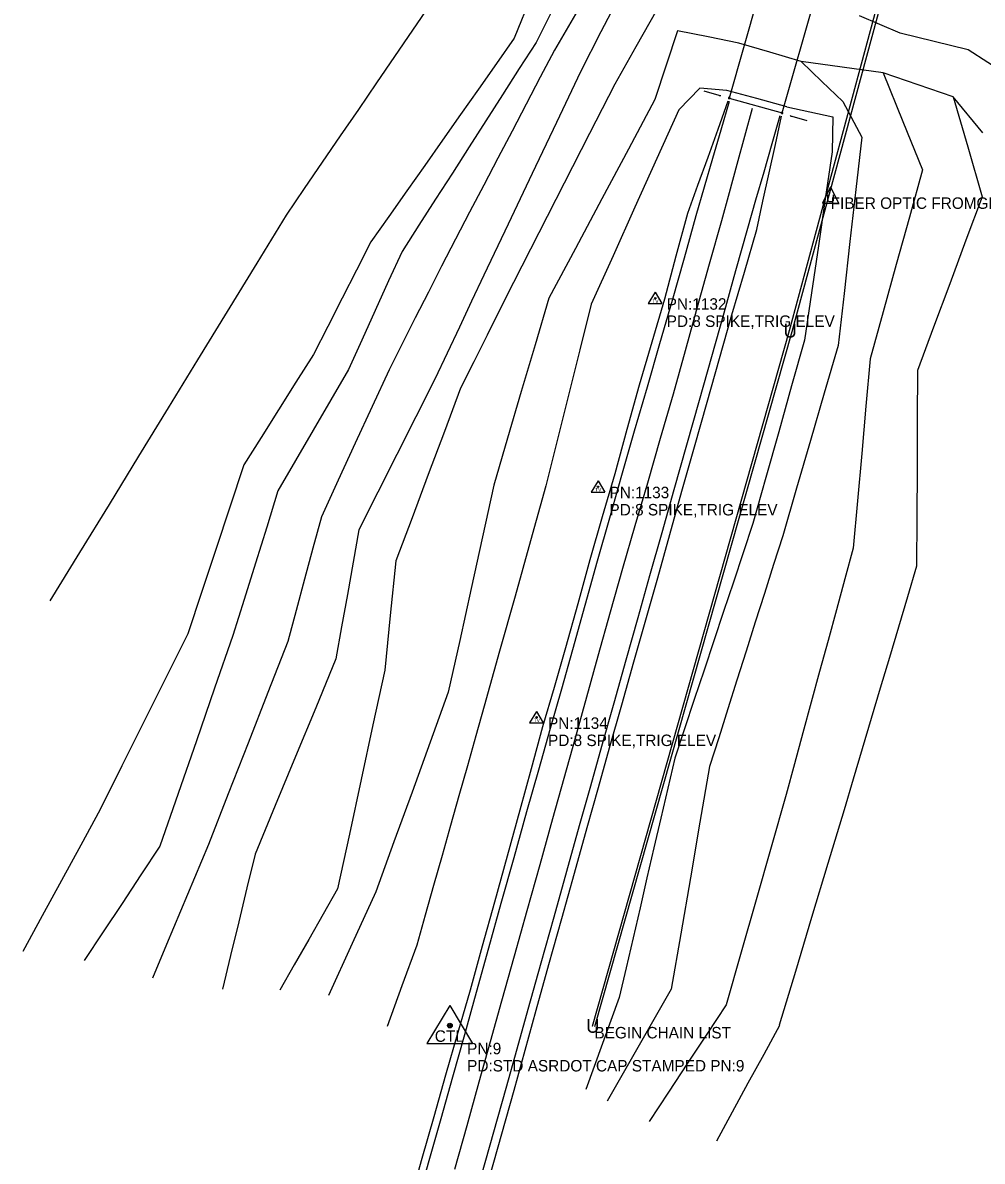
# Model space of a CAD drawing. Extents: x 1445297 to 1476720, y 2042269 to 2057889.
# Drawn here: x 1445766.9 to 1446184.7, y 2055038.2 to 2055534.2 of the extents above; entities that cross this region are included whole.
import ezdxf

# ---------------------------------------------------------------- set-up
doc = ezdxf.new("R2010")
doc.units = 0
for name, color, linetype in [('S_BRIDGE', 7, 'Continuous'), ('S_DITCHLINE', 7, 'Continuous'), ('S_EDGE_PAVEMENT', 7, 'Continuous'), ('S_FIBER_OPTIC_CABLE', 7, 'Continuous'), ('S_PAVEMENT_CROWN', 7, 'Continuous'), ('S_PRIMARY_CTL', 7, 'Continuous'), ('S_PRIMARY_CTL_ANNOT', 7, 'Continuous'), ('S_SECONDARY_CTL', 7, 'Continuous'), ('S_SECONDARY_CTL_ANNOT', 7, 'Continuous'), ('S_SHOULDER', 7, 'Continuous'), ('S_STR_PT_SYM', 7, 'Continuous'), ('S_STREAM', 7, 'Continuous'), ('S_TREE', 7, 'Continuous'), ('S_UNDERGROUND_CABLE', 7, 'Continuous'), ('S_UNDERGROUND_CABLE_ANNOT', 7, 'Continuous'), ('S_UTILITY_POLE', 7, 'Continuous'), ('S_UTILITY_POLE_ANNOT', 7, 'Continuous'), ('S_UTL_PT_SYM', 7, 'Continuous'), ('S_WALL', 7, 'Continuous')]:
    doc.layers.add(name, color=color, linetype=linetype)

msp = doc.modelspace()

# ---------------------------------------------------------------- linework, layer by layer
at = {"layer": 'S_BRIDGE'}
for p, q in [((1446101.76, 2055597.5), (1446074.53, 2055501.41)), ((1446097.53, 2055494.89), (1446124.93, 2055591.15)), ((1446074.53, 2055501.41), (1446097.53, 2055494.89))]:
    msp.add_line(p, q, dxfattribs=at)
at = {"layer": 'S_DITCHLINE'}
for points in [[(1445988.57, 2055546.55), (1445980.92, 2055527.54), (1445973.11, 2055516.44), (1445965.31, 2055505.33), (1445957.5, 2055494.23), (1445949.7, 2055483.12), (1445941.9, 2055472.01), (1445934.09, 2055460.91), (1445926.29, 2055449.8), (1445918.48, 2055438.7), (1445912.22, 2055426.43), (1445905.96, 2055414.17), (1445899.69, 2055401.91), (1445893.43, 2055389.65), (1445885.85, 2055377.62), (1445878.27, 2055365.6), (1445870.68, 2055353.57), (1445863.1, 2055341.54), (1445857, 2055323.16), (1445850.91, 2055304.77), (1445844.81, 2055286.38), (1445838.72, 2055268), (1445829.17, 2055248.84), (1445819.63, 2055229.69), (1445810.08, 2055210.54), (1445800.54, 2055191.39), (1445792.12, 2055175.95), (1445783.71, 2055160.5), (1445775.29, 2055145.06), (1445766.88, 2055129.62)], [(1446027.55, 2055547.55), (1446018.67, 2055530.18), (1446009.78, 2055512.82), (1445999.25, 2055490.68), (1445988.72, 2055468.55), (1445978.18, 2055446.41), (1445967.65, 2055424.28), (1445962.32, 2055412.94), (1445957, 2055401.61), (1445951.67, 2055390.28), (1445946.34, 2055378.95), (1445938.05, 2055362.52), (1445929.76, 2055346.09), (1445921.47, 2055329.66), (1445913.19, 2055313.23), (1445910.7, 2055299.18), (1445908.22, 2055285.14), (1445905.74, 2055271.1), (1445903.25, 2055257.05), (1445894.45, 2055235.78), (1445885.65, 2055214.52), (1445876.84, 2055193.25), (1445868.04, 2055171.98), (1445864.49, 2055157.27), (1445860.94, 2055142.56), (1445857.39, 2055127.85), (1445853.84, 2055113.14)], [(1445999.14, 2055543.07), (1445990.41, 2055525.62), (1445983.11, 2055514.25), (1445975.82, 2055502.87), (1445968.53, 2055491.49), (1445961.24, 2055480.12), (1445953.94, 2055468.74), (1445946.65, 2055457.36), (1445939.36, 2055445.99), (1445932.06, 2055434.61), (1445926.21, 2055421.73), (1445920.36, 2055408.85), (1445914.51, 2055395.98), (1445908.66, 2055383.1), (1445900.99, 2055369.88), (1445893.33, 2055356.66), (1445885.66, 2055343.45), (1445878, 2055330.23), (1445873.1, 2055314.48), (1445868.2, 2055298.72), (1445863.31, 2055282.97), (1445858.41, 2055267.21), (1445850.43, 2055244.26), (1445842.46, 2055221.31), (1445834.48, 2055198.35), (1445826.5, 2055175.4), (1445818.3, 2055162.96), (1445810.09, 2055150.52), (1445801.88, 2055138.09), (1445793.67, 2055125.65)], [(1446008.57, 2055539.67), (1445998.37, 2055522.29), (1445992.22, 2055510.53), (1445986.07, 2055498.77), (1445979.92, 2055487.01), (1445973.77, 2055475.25), (1445967.63, 2055463.48), (1445961.48, 2055451.72), (1445955.33, 2055439.96), (1445949.18, 2055428.2), (1445943.5, 2055416.9), (1445937.81, 2055405.6), (1445932.13, 2055394.31), (1445926.44, 2055383.01), (1445919.06, 2055366.99), (1445911.67, 2055350.98), (1445904.29, 2055334.96), (1445896.9, 2055318.94), (1445893.24, 2055305.35), (1445889.58, 2055291.76), (1445885.92, 2055278.17), (1445882.26, 2055264.57), (1445873.63, 2055242.48), (1445864.99, 2055220.38), (1445856.36, 2055198.29), (1445847.72, 2055176.19), (1445841.63, 2055161.65), (1445835.55, 2055147.11), (1445829.46, 2055132.56), (1445823.38, 2055118.02)], [(1446043.06, 2055539.85), (1446033.86, 2055523.68), (1446024.67, 2055507.52), (1446013.65, 2055485.92), (1446002.62, 2055464.32), (1445991.6, 2055442.71), (1445980.57, 2055421.11), (1445974.81, 2055409.58), (1445969.05, 2055398.04), (1445963.29, 2055386.51), (1445957.53, 2055374.97), (1445950.48, 2055356.16), (1445943.44, 2055337.35), (1445936.39, 2055318.54), (1445929.35, 2055299.73), (1445926.93, 2055275.96), (1445924.51, 2055252.18), (1445919.38, 2055228.36), (1445914.25, 2055204.54), (1445909.12, 2055180.73), (1445903.99, 2055156.91), (1445897.7, 2055145.86), (1445891.42, 2055134.82), (1445885.13, 2055123.77), (1445878.85, 2055112.73)], [(1446299.1, 2055378.25), (1446294.17, 2055392.37), (1446289.24, 2055406.49), (1446284.31, 2055420.62), (1446279.38, 2055434.74), (1446269.61, 2055451.33), (1446259.85, 2055467.93), (1446248.1, 2055476.05), (1446236.35, 2055484.18), (1446224.6, 2055492.31), (1446212.84, 2055500.44), (1446195.69, 2055511.4), (1446178.54, 2055522.35), (1446163.75, 2055526.02), (1446148.96, 2055529.68), (1446131.24, 2055537.2)], [(1446184.97, 2055486.27), (1446172.06, 2055501.87), (1446156.84, 2055507.13), (1446141.62, 2055512.4), (1446123.7, 2055514.86), (1446105.78, 2055517.32), (1446092.22, 2055521.34), (1446078.67, 2055525.35), (1446065.36, 2055528.04), (1446052.05, 2055530.73), (1446047.12, 2055515.74), (1446042.18, 2055500.74), (1446030.62, 2055479.1), (1446019.06, 2055457.47), (1446007.5, 2055435.83), (1445995.94, 2055414.2), (1445989.95, 2055393.85), (1445983.96, 2055373.51), (1445977.98, 2055353.16), (1445971.99, 2055332.82), (1445967.04, 2055310.24), (1445962.09, 2055287.67), (1445957.14, 2055265.1), (1445952.19, 2055242.52), (1445944.3, 2055220.78), (1445936.41, 2055199.04), (1445928.52, 2055177.3), (1445920.63, 2055155.56), (1445910.33, 2055133), (1445900.04, 2055110.44)], [(1446105.78, 2055517.32), (1446114.85, 2055508.59), (1446123.92, 2055499.85), (1446132.27, 2055484.3), (1446129.68, 2055461.62), (1446127.1, 2055438.95), (1446124.51, 2055416.27), (1446121.93, 2055393.59), (1446115.9, 2055372.87), (1446109.88, 2055352.15), (1446103.86, 2055331.44), (1446097.83, 2055310.72), (1446093.85, 2055298.14), (1446089.86, 2055285.57), (1446085.87, 2055272.99), (1446081.88, 2055260.42), (1446077.9, 2055247.85), (1446073.91, 2055235.27), (1446069.92, 2055222.7), (1446065.93, 2055210.12), (1446061.77, 2055185.87), (1446057.6, 2055161.61), (1446053.43, 2055137.35), (1446049.27, 2055113.1), (1446042.28, 2055100.91), (1446035.29, 2055088.73), (1446028.3, 2055076.54), (1446021.32, 2055064.36)], [(1446141.62, 2055512.4), (1446150.13, 2055491.25), (1446158.65, 2055470.11), (1446152.95, 2055449.52), (1446147.25, 2055428.92), (1446141.56, 2055408.33), (1446135.86, 2055387.74), (1446134.03, 2055367.13), (1446132.19, 2055346.52), (1446130.36, 2055325.91), (1446128.53, 2055305.29), (1446124.87, 2055291.88), (1446121.21, 2055278.47), (1446117.55, 2055265.05), (1446113.89, 2055251.64), (1446110.23, 2055238.23), (1446106.57, 2055224.81), (1446102.91, 2055211.4), (1446099.25, 2055197.98), (1446092.73, 2055175.07), (1446086.21, 2055152.15), (1446079.69, 2055129.23), (1446073.17, 2055106.32), (1446064.78, 2055093.62), (1446056.4, 2055080.93), (1446048.01, 2055068.24), (1446039.62, 2055055.54)], [(1446172.06, 2055501.87), (1446178.36, 2055480.12), (1446184.67, 2055458.37), (1446177.62, 2055439.44), (1446170.58, 2055420.51), (1446163.54, 2055401.58), (1446156.49, 2055382.65), (1446156.39, 2055361.34), (1446156.29, 2055340.03), (1446156.18, 2055318.71), (1446156.08, 2055297.4), (1446152.13, 2055284.14), (1446148.19, 2055270.88), (1446144.24, 2055257.63), (1446140.3, 2055244.37), (1446136.35, 2055231.11), (1446132.4, 2055217.85), (1446128.46, 2055204.59), (1446124.51, 2055191.34), (1446117.46, 2055167.87), (1446110.41, 2055144.4), (1446103.35, 2055120.93), (1446096.3, 2055097.47), (1446096.42, 2055097.31), (1446089.55, 2055084.73), (1446082.67, 2055072.16), (1446075.8, 2055059.58), (1446068.92, 2055047.01)]]:
    msp.add_lwpolyline(points, dxfattribs=at)
at = {"layer": 'S_EDGE_PAVEMENT'}
for points in [[(1445938.52, 2055019.41), (1445943.91, 2055038.59), (1445949.02, 2055056.8), (1445954.14, 2055075), (1445959.31, 2055093.43), (1445964.48, 2055111.86), (1445969.86, 2055131.22), (1445975.25, 2055150.57), (1445980.84, 2055170.55), (1445986.44, 2055190.52), (1445991.57, 2055208.73), (1445996.69, 2055226.94), (1446001.56, 2055244.03), (1446006.42, 2055261.13), (1446011.8, 2055280.47), (1446017.18, 2055299.81), (1446022.46, 2055318.48), (1446027.74, 2055337.15), (1446033.32, 2055356.41), (1446038.9, 2055375.66), (1446044.33, 2055394.51), (1446049.75, 2055413.35), (1446054.97, 2055431.76), (1446060.19, 2055450.18), (1446063.78, 2055462.66), (1446067.38, 2055475.14), (1446070.97, 2055487.62), (1446074.57, 2055500.1)], [(1445966.63, 2055031.96), (1445972, 2055050.98), (1445977.38, 2055070), (1445982.18, 2055087.21), (1445986.99, 2055104.42), (1445992.66, 2055124.59), (1445998.34, 2055144.75), (1446003.86, 2055164.59), (1446009.38, 2055184.42), (1446014.22, 2055201.76), (1446019.06, 2055219.09), (1446024.38, 2055237.9), (1446029.69, 2055256.71), (1446034.84, 2055275.06), (1446040, 2055293.4), (1446045.26, 2055312.15), (1446050.52, 2055330.9), (1446056.07, 2055350.31), (1446061.63, 2055369.72), (1446066.95, 2055388.81), (1446072.28, 2055407.89), (1446077.46, 2055426.31), (1446082.64, 2055444.73), (1446086.15, 2055457), (1446089.66, 2055469.27), (1446093.17, 2055481.53), (1446096.68, 2055493.8)]]:
    msp.add_lwpolyline(points, dxfattribs=at)
at = {"layer": 'S_FIBER_OPTIC_CABLE'}
for p, q in [((1446184.54, 2055711.05), (1446100.6, 2055399.96)), ((1446100.6, 2055399.96), (1446014.81, 2055096.89))]:
    msp.add_line(p, q, dxfattribs=at)
at = {"layer": 'S_PAVEMENT_CROWN'}
msp.add_lwpolyline([(1445955.04, 2055034.8), (1445960.36, 2055053.8), (1445965.68, 2055072.8), (1445970.62, 2055090.43), (1445975.55, 2055108.06), (1445981.04, 2055127.75), (1445986.52, 2055147.44), (1445992.13, 2055167.46), (1445997.74, 2055187.48), (1446002.62, 2055205.06), (1446007.5, 2055222.64), (1446012.49, 2055240.54), (1446017.48, 2055258.43), (1446022.82, 2055277.53), (1446028.17, 2055296.63), (1446033.61, 2055315.21), (1446039.06, 2055333.8), (1446044.63, 2055353.17), (1446050.21, 2055372.54), (1446055.42, 2055391.46), (1446060.63, 2055410.38), (1446065.94, 2055429.2), (1446071.24, 2055448.02), (1446074.59, 2055460.28), (1446077.95, 2055472.53), (1446081.3, 2055484.79), (1446084.66, 2055497.04)], dxfattribs=at)
at = {"layer": 'S_PRIMARY_CTL'}
for p, q in [((1445952.88, 2055106.01), (1445942.84, 2055089.5)), ((1445952.88, 2055106.01), (1445962.7, 2055089.5)), ((1445942.84, 2055089.5), (1445962.7, 2055089.5))]:
    msp.add_line(p, q, dxfattribs=at)
for radius in [1.04, 0.609, 0.344]:
    msp.add_circle((1445952.88, 2055097.31), radius, dxfattribs=at)
at = {"layer": 'S_SECONDARY_CTL'}
for p, q in [((1446042.29, 2055416.8), (1446039.28, 2055411.84)), ((1446042.29, 2055416.8), (1446045.24, 2055411.84)), ((1446039.28, 2055411.84), (1446045.24, 2055411.84)), ((1446017.37, 2055334.67), (1446014.36, 2055329.72)), ((1446017.37, 2055334.67), (1446020.32, 2055329.72)), ((1446014.36, 2055329.72), (1446020.32, 2055329.72)), ((1445990.61, 2055234.19), (1445987.6, 2055229.24)), ((1445990.61, 2055234.19), (1445993.56, 2055229.24)), ((1445987.6, 2055229.24), (1445993.56, 2055229.24))]:
    msp.add_line(p, q, dxfattribs=at)
for centre, radius in [((1446042.29, 2055414.19), 0.311), ((1446042.29, 2055414.19), 0.183), ((1446042.29, 2055414.19), 0.103), ((1446017.37, 2055332.06), 0.311), ((1446017.37, 2055332.06), 0.183), ((1446017.37, 2055332.06), 0.103), ((1445990.61, 2055231.58), 0.311), ((1445990.61, 2055231.58), 0.183), ((1445990.61, 2055231.58), 0.103)]:
    msp.add_circle(centre, radius, dxfattribs=at)
at = {"layer": 'S_SHOULDER'}
for points in [[(1445935.44, 2055020.19), (1445940.83, 2055039.53), (1445945.97, 2055057.7), (1445951.1, 2055075.86), (1445956.46, 2055094.41), (1445961.81, 2055112.95), (1445967.1, 2055132.08), (1445972.39, 2055151.21), (1445977.9, 2055171.22), (1445983.41, 2055191.23), (1445988.41, 2055209.38), (1445993.41, 2055227.54), (1445998.4, 2055244.79), (1446003.4, 2055262.04), (1446008.68, 2055281.23), (1446013.96, 2055300.43), (1446019.38, 2055319.14), (1446024.8, 2055337.86), (1446030.12, 2055357.13), (1446035.44, 2055376.41), (1446040.93, 2055395.19), (1446046.42, 2055413.98), (1446051.43, 2055432.59), (1446056.44, 2055451.2), (1446060.86, 2055463.43), (1446065.28, 2055475.66), (1446069.7, 2055487.89), (1446074.12, 2055500.12)], [(1445970.08, 2055031.1), (1445975.49, 2055050.1), (1445980.9, 2055069.1), (1445985.66, 2055086.55), (1445990.43, 2055104), (1445996, 2055123.95), (1446001.58, 2055143.91), (1446007.11, 2055163.77), (1446012.64, 2055183.63), (1446017.52, 2055201), (1446022.4, 2055218.36), (1446027.72, 2055237.04), (1446033.04, 2055255.71), (1446038.24, 2055274.07), (1446043.43, 2055292.43), (1446048.62, 2055311.29), (1446053.82, 2055330.14), (1446059.39, 2055349.51), (1446064.96, 2055368.88), (1446070.33, 2055387.89), (1446075.7, 2055406.9), (1446081.1, 2055425.49), (1446086.51, 2055444.08), (1446089.21, 2055456.43), (1446091.91, 2055468.79), (1446094.61, 2055481.15), (1446097.31, 2055493.5)]]:
    msp.add_lwpolyline(points, dxfattribs=at)
at = {"layer": 'S_STR_PT_SYM'}
for points in [[(1446074.53, 2055501.41), (1446074.53, 2055501.91), (1446074.53, 2055501.41), (1446074.03, 2055501.41), (1446074.53, 2055501.41), (1446074.53, 2055500.91), (1446074.53, 2055501.41), (1446075.03, 2055501.41)], [(1446097.53, 2055494.89), (1446097.53, 2055495.39), (1446097.53, 2055494.89), (1446097.03, 2055494.89), (1446097.53, 2055494.89), (1446097.53, 2055494.39), (1446097.53, 2055494.89), (1446098.03, 2055494.89)]]:
    msp.add_lwpolyline(points, dxfattribs=at)
at = {"layer": 'S_STREAM'}
for points in [[(1446099.67, 2055497.56), (1446086.54, 2055501.16), (1446073.41, 2055504.76), (1446061.66, 2055505.66), (1446052.52, 2055496.25), (1446042.98, 2055475.07), (1446033.45, 2055453.9), (1446023.92, 2055432.73), (1446014.39, 2055411.56), (1446009.46, 2055391.78), (1446004.52, 2055372), (1445999.59, 2055352.21), (1445994.65, 2055332.43), (1445987.95, 2055308.45), (1445981.24, 2055284.46), (1445974.53, 2055260.48), (1445967.82, 2055236.49), (1445964.15, 2055223.47), (1445960.48, 2055210.45), (1445956.81, 2055197.43), (1445953.14, 2055184.41), (1445949.47, 2055171.39), (1445945.8, 2055158.37), (1445942.13, 2055145.34), (1445938.46, 2055132.32), (1445932.01, 2055114.63), (1445925.56, 2055096.94)], [(1446099.67, 2055497.56), (1446119.58, 2055493.17), (1446119.31, 2055477.97), (1446116.31, 2055457.48), (1446113.32, 2055436.98), (1446110.32, 2055416.48), (1446107.32, 2055395.99), (1446101.7, 2055376.02), (1446096.08, 2055356.04), (1446090.46, 2055336.07), (1446084.84, 2055316.1), (1446080.58, 2055303.31), (1446076.32, 2055290.53), (1446072.06, 2055277.74), (1446067.81, 2055264.95), (1446063.55, 2055252.17), (1446059.29, 2055239.38), (1446055.03, 2055226.59), (1446050.77, 2055213.81), (1446047.75, 2055200.77), (1446044.73, 2055187.73), (1446041.71, 2055174.69), (1446038.68, 2055161.65), (1446035.66, 2055148.61), (1446032.64, 2055135.57), (1446029.61, 2055122.53), (1446026.59, 2055109.49), (1446019.31, 2055089.5), (1446012.03, 2055069.52)]]:
    msp.add_lwpolyline(points, dxfattribs=at)
at = {"layer": 'S_TREE'}
msp.add_lwpolyline([(1445944.45, 2055542.5), (1445936.59, 2055530.99), (1445928.73, 2055519.49), (1445920.88, 2055507.98), (1445913.02, 2055496.47), (1445905.16, 2055484.97), (1445897.3, 2055473.46), (1445889.44, 2055461.96), (1445881.58, 2055450.45), (1445868.73, 2055429.44), (1445855.87, 2055408.42), (1445843.01, 2055387.41), (1445830.15, 2055366.39), (1445817.29, 2055345.38), (1445804.43, 2055324.37), (1445791.57, 2055303.35), (1445778.72, 2055282.34)], dxfattribs=at)
at = {"layer": 'S_UNDERGROUND_CABLE'}
for p, q in [((1446186.26, 2055711.49), (1446101.82, 2055399.59)), ((1446101.82, 2055399.59), (1446015.83, 2055096.71))]:
    msp.add_line(p, q, dxfattribs=at)
at = {"layer": 'S_UTILITY_POLE'}
for p, q in [((1446118.68, 2055462.67), (1446115.16, 2055455.57)), ((1446118.68, 2055462.67), (1446122.17, 2055455.57)), ((1446115.16, 2055455.57), (1446122.17, 2055455.57)), ((1446117.48, 2055456.81), (1446117.48, 2055459.26)), ((1446118.1, 2055456.16), (1446117.48, 2055456.81)), ((1446119.3, 2055456.16), (1446118.1, 2055456.16)), ((1446119.85, 2055456.81), (1446119.3, 2055456.16)), ((1446119.85, 2055459.26), (1446119.85, 2055456.81))]:
    msp.add_line(p, q, dxfattribs=at)
at = {"layer": 'S_UTL_PT_SYM'}
for points in [[(1446100.6, 2055399.96), (1446100.6, 2055400.01), (1446100.6, 2055399.96), (1446100.55, 2055399.96), (1446100.6, 2055399.96), (1446100.6, 2055399.91), (1446100.6, 2055399.96), (1446100.66, 2055399.96)], [(1446014.81, 2055096.89), (1446014.81, 2055096.94), (1446014.81, 2055096.89), (1446014.76, 2055096.89), (1446014.81, 2055096.89), (1446014.81, 2055096.84), (1446014.81, 2055096.89), (1446014.86, 2055096.89)]]:
    msp.add_lwpolyline(points, dxfattribs=at)
at = {"layer": 'S_WALL'}
for points in [[(1446070.83, 2055502.3), (1446070.31, 2055502.41), (1446070.11, 2055502.46), (1446063.58, 2055504.34)], [(1446101.09, 2055493.73), (1446101.39, 2055493.56), (1446101.71, 2055493.49), (1446108.38, 2055491.65)]]:
    msp.add_lwpolyline(points, dxfattribs=at)

# ---------------------------------------------------------------- texts
at = {"layer": 'S_PRIMARY_CTL'}
msp.add_text('CTL', height=5, dxfattribs=at).set_placement((1445946.29, 2055090.23))
at = {"layer": 'S_PRIMARY_CTL_ANNOT'}
for s, p in [('PN:9', (1445960.38, 2055084.81)), ('PD:STD ASRDOT CAP STAMPED PN:9', (1445960.38, 2055077.31))]:
    msp.add_text(s, height=5, dxfattribs=at).set_placement(p)
at = {"layer": 'S_SECONDARY_CTL'}
for p in [(1446041.09, 2055412.18), (1446016.17, 2055330.05), (1445989.41, 2055229.57)]:
    msp.add_text('TV', height=1.5, dxfattribs=at).set_placement(p)
at = {"layer": 'S_SECONDARY_CTL_ANNOT'}
for s, p in [('PN:1132', (1446047.29, 2055409.19)), ('PD:8 SPIKE,TRIG ELEV', (1446047.29, 2055401.69)), ('PN:1133', (1446022.37, 2055327.06)), ('PD:8 SPIKE,TRIG ELEV', (1446022.37, 2055319.56)), ('PN:1134', (1445995.61, 2055226.58)), ('PD:8 SPIKE,TRIG ELEV', (1445995.61, 2055219.08))]:
    msp.add_text(s, height=5, dxfattribs=at).set_placement(p)
at = {"layer": 'S_UNDERGROUND_CABLE_ANNOT'}
msp.add_text('BEGIN CHAIN LIST', height=5, dxfattribs=at).set_placement((1446015.83, 2055091.71))
at = {"layer": 'S_UTILITY_POLE_ANNOT'}
msp.add_text('FIBER OPTIC FROMGENERAL', height=5, dxfattribs=at).set_placement((1446118.68, 2055453.13))
at = {"layer": 'S_UTL_PT_SYM'}
for p in [(1446098.19, 2055397.04), (1446012.2, 2055094.17)]:
    msp.add_text('U', height=6, dxfattribs=at).set_placement(p)

doc.saveas('drawing.dxf')
